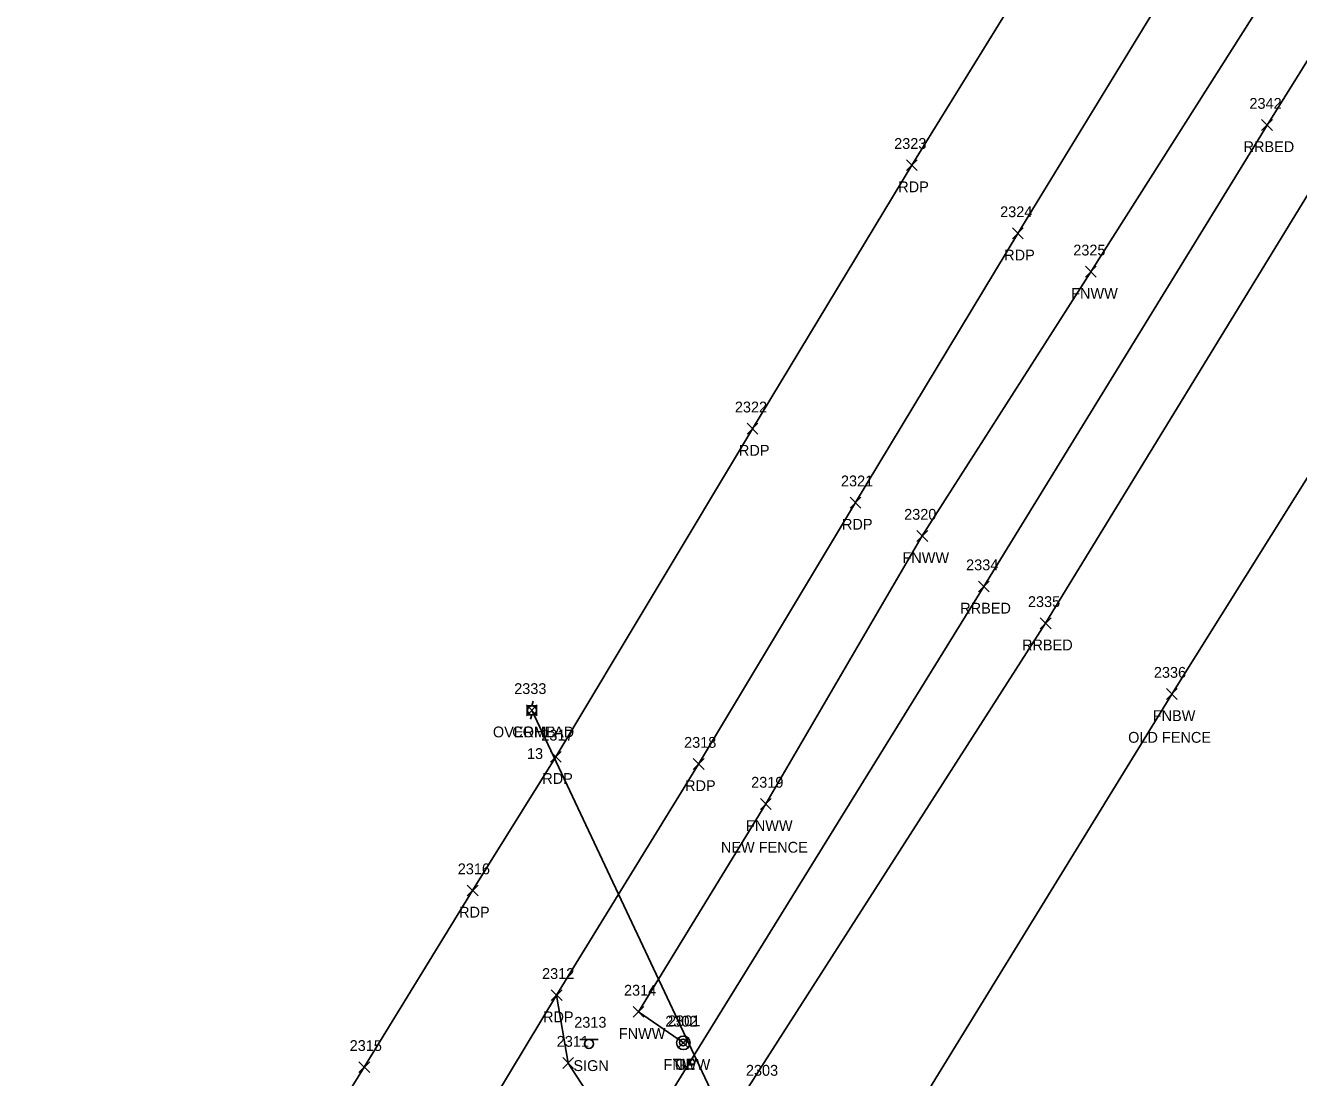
# Model space of a CAD drawing. Extents: x 1508122 to 1515053, y 865012 to 875267.
# Drawn here: x 1513728.5 to 1513963.5, y 873736 to 873930.3 of the extents above; entities that cross this region are included whole.
import ezdxf

# ---------------------------------------------------------------- set-up
doc = ezdxf.new("R2010")
doc.units = 0
for name, color, linetype in [('C_A', 7, 'Continuous'), ('C_I', 7, 'Continuous'), ('CBP', 7, 'Continuous'), ('L_A', 7, 'Continuous'), ('L_C', 7, 'Continuous'), ('L_I', 7, 'Continuous'), ('L_TIC', 7, 'Continuous'), ('LFNC', 7, 'Continuous'), ('P_A', 7, 'Continuous'), ('P_I', 7, 'Continuous'), ('P_TIC', 7, 'Continuous'), ('PET', 7, 'Continuous'), ('R_A', 7, 'Continuous'), ('R_I', 7, 'Continuous'), ('R_TIC', 7, 'Continuous'), ('RGP', 7, 'Continuous'), ('RRB', 7, 'Continuous'), ('S_A', 7, 'Continuous'), ('S_I', 7, 'Continuous'), ('SSGN', 7, 'Continuous'), ('U_A', 7, 'Continuous'), ('U_C', 7, 'Continuous'), ('U_I', 7, 'Continuous'), ('U_TIC', 7, 'Continuous'), ('UP', 7, 'Continuous'), ('UT', 7, 'Continuous')]:
    doc.layers.add(name, color=color, linetype=linetype)

msp = doc.modelspace()

# ---------------------------------------------------------------- linework, layer by layer
at = {"layer": 'CBP'}
for radius in [0.625, 0.0833]:
    msp.add_circle((1513849.87, 873742.45), radius, dxfattribs=at)
at = {"layer": 'L_TIC'}
for points in [[(1513924.17, 873883.81), (1513926.17, 873885.81)], [(1513926.17, 873883.81), (1513924.17, 873885.81)], [(1513893.04, 873835), (1513895.04, 873837)], [(1513895.04, 873835), (1513893.04, 873837)], [(1513939.11, 873805.81), (1513941.11, 873807.81)], [(1513941.11, 873805.81), (1513939.11, 873807.81)], [(1513864.15, 873785.51), (1513866.15, 873787.51)], [(1513866.15, 873785.51), (1513864.15, 873787.51)], [(1513840.67, 873747.1), (1513842.67, 873749.1)], [(1513842.67, 873747.1), (1513840.67, 873749.1)], [(1513848.94, 873741.38), (1513850.94, 873743.38)], [(1513850.94, 873741.38), (1513848.94, 873743.38)]]:
    msp.add_lwpolyline(points, dxfattribs=at)
at = {"layer": 'LFNC'}
for points in [[(1513849.94, 873742.38), (1513841.67, 873748.1), (1513865.15, 873786.51), (1513894.04, 873836), (1513925.17, 873884.81), (1513957.31, 873935.58), (1513979.46, 873971.1), (1514010.28, 874020.55), (1514050.39, 874085.13), (1514079.4, 874132.28), (1514109.16, 874179.83), (1514120.56, 874178.77)], [(1513883.96, 873715.43), (1513940.11, 873806.81), (1513990.41, 873887.15)]]:
    msp.add_lwpolyline(points, dxfattribs=at)
at = {"layer": 'P_TIC'}
for points in [[(1513891.11, 873903.49), (1513893.11, 873905.49)], [(1513893.11, 873903.49), (1513891.11, 873905.49)], [(1513910.67, 873890.89), (1513912.67, 873892.89)], [(1513912.67, 873890.89), (1513910.67, 873892.89)], [(1513861.7, 873854.82), (1513863.7, 873856.82)], [(1513863.7, 873854.82), (1513861.7, 873856.82)], [(1513880.72, 873841.17), (1513882.72, 873843.17)], [(1513882.72, 873841.17), (1513880.72, 873843.17)], [(1513825.41, 873794.21), (1513827.41, 873796.21)], [(1513827.41, 873794.21), (1513825.41, 873796.21)], [(1513851.76, 873792.88), (1513853.76, 873794.88)], [(1513853.76, 873792.88), (1513851.76, 873794.88)], [(1513810.04, 873769.52), (1513812.04, 873771.52)], [(1513812.04, 873769.52), (1513810.04, 873771.52)], [(1513825.54, 873750.18), (1513827.54, 873752.18)], [(1513827.54, 873750.18), (1513825.54, 873752.18)], [(1513825.54, 873750.18), (1513827.54, 873752.18)], [(1513827.54, 873750.18), (1513825.54, 873752.18)], [(1513790.03, 873736.88), (1513792.03, 873738.88)], [(1513792.03, 873736.88), (1513790.03, 873738.88)], [(1513827.68, 873737.66), (1513829.68, 873739.66)], [(1513829.68, 873737.66), (1513827.68, 873739.66)]]:
    msp.add_lwpolyline(points, dxfattribs=at)
at = {"layer": 'PET'}
for points in [[(1513466.17, 873213.07), (1513500.31, 873271.08), (1513533.51, 873325.85), (1513565.92, 873377.51), (1513601.02, 873434.43), (1513630.8, 873481.59), (1513663.12, 873532.69), (1513695.04, 873583.32), (1513791.03, 873737.88), (1513811.04, 873770.52), (1513826.41, 873795.21), (1513862.7, 873855.82), (1513892.11, 873904.49), (1513923.1, 873954.81)], [(1513455.04, 873151.27), (1513485.29, 873202.33), (1513519.6, 873259.87), (1513551.9, 873312.77), (1513584.37, 873365.63), (1513617.09, 873418.81), (1513648.76, 873468.83), (1513681.49, 873520.59), (1513713.49, 873570.94), (1513800.66, 873708.29), (1513826.54, 873751.18), (1513852.76, 873793.88), (1513881.72, 873842.17), (1513911.67, 873891.89), (1513942.82, 873942.89)], [(1513824.54, 873545.65), (1513854.29, 873593.15), (1513872.35, 873622.16), (1513878.19, 873633.02), (1513885.6, 873656.94), (1513886.44, 873668.48), (1513875.83, 873692.09), (1513868.29, 873700.88), (1513850.37, 873716.18), (1513841.18, 873722.67), (1513834.12, 873730.17), (1513828.68, 873738.66), (1513826.54, 873751.18)]]:
    msp.add_lwpolyline(points, dxfattribs=at)
at = {"layer": 'R_TIC'}
for points in [[(1513956.69, 873910.9), (1513958.69, 873912.9)], [(1513958.69, 873910.9), (1513956.69, 873912.9)], [(1513904.39, 873825.67), (1513906.39, 873827.67)], [(1513906.39, 873825.67), (1513904.39, 873827.67)], [(1513915.81, 873818.88), (1513917.81, 873820.88)], [(1513917.81, 873818.88), (1513915.81, 873820.88)]]:
    msp.add_lwpolyline(points, dxfattribs=at)
at = {"layer": 'RGP'}
msp.add_line((1513849.94, 873742.38), (1513849.94, 873742.38), dxfattribs=at)
for radius in [1.25, 0.0833]:
    msp.add_circle((1513849.94, 873742.38), radius, dxfattribs=at)
at = {"layer": 'RRB'}
for points in [[(1513228.31, 872677.99), (1513247.91, 872725.05), (1513270.86, 872775.34), (1513289.12, 872813.81), (1513319.1, 872873.87), (1513347.47, 872925.52), (1513374.77, 872971.44), (1513393.49, 873000.11), (1513437.27, 873071.02), (1513458.13, 873103.89), (1513504.32, 873179.38), (1513525.85, 873213.8), (1513574, 873293.73), (1513619.17, 873366.93), (1513650.95, 873417.63), (1513697.43, 873492.91), (1513723.07, 873532.74), (1513749.97, 873575.84), (1513797.76, 873652.14), (1513828.99, 873702.68), (1513841.18, 873722.67), (1513905.39, 873826.67), (1513957.69, 873911.9), (1513997.47, 873975.73)], [(1513240.34, 872672.59), (1513259.24, 872718.12), (1513282.12, 872769.92), (1513300.61, 872809.77), (1513331.29, 872869.64), (1513358.47, 872918.38), (1513387.89, 872964.97), (1513404.26, 872991.91), (1513448.93, 873064.4), (1513469.17, 873096.67), (1513514.98, 873172.69), (1513538.39, 873208.28), (1513585.22, 873287.66), (1513630.12, 873359.27), (1513661.28, 873410.15), (1513709.31, 873487.04), (1513733.32, 873526.23), (1513760.83, 873569.62), (1513809.55, 873645.89), (1513841.33, 873697.41), (1513850.37, 873716.18), (1513916.81, 873819.88), (1513968.56, 873904.51), (1514007.95, 873968.59)]]:
    msp.add_lwpolyline(points, dxfattribs=at)
at = {"layer": 'SSGN'}
for p, q in [((1513830.85, 873743.03), (1513834.19, 873743.03)), ((1513832.5, 873742.2), (1513832.5, 873742.2))]:
    msp.add_line(p, q, dxfattribs=at)
msp.add_circle((1513832.5, 873742.2), 0.833, dxfattribs=at)
at = {"layer": 'U_TIC'}
for points in [[(1513820.97, 873802.81), (1513822.97, 873804.81)], [(1513822.97, 873802.81), (1513820.97, 873804.81)]]:
    msp.add_lwpolyline(points, dxfattribs=at)
at = {"layer": 'UP'}
for p, q in [((1513821.13, 873802.98), (1513821.13, 873804.64)), ((1513821.13, 873804.64), (1513822.8, 873804.64)), ((1513822.22, 873805.48), (1513821.97, 873804.64)), ((1513822.8, 873804.64), (1513822.8, 873802.98)), ((1513822.8, 873802.98), (1513821.13, 873802.98)), ((1513821.72, 873802.14), (1513821.97, 873802.98)), ((1513821.97, 873803.81), (1513821.97, 873803.81))]:
    msp.add_line(p, q, dxfattribs=at)
msp.add_circle((1513821.97, 873803.81), 0.833, dxfattribs=at)
at = {"layer": 'UT'}
msp.add_lwpolyline([(1513894.86, 873648.9), (1513821.97, 873803.81)], dxfattribs=at)

# ---------------------------------------------------------------- texts
at = {"layer": 'C_A'}
msp.add_text('TIE', height=2, dxfattribs=at).set_placement((1513847.95, 873737.45))
at = {"layer": 'C_I'}
msp.add_text('2301', height=2, dxfattribs=at).set_placement((1513847.1, 873745.45))
at = {"layer": 'L_A'}
for s, p in [('FNWW', (1513921.52, 873879.81)), ('FNWW', (1513890.38, 873831)), ('FNBW', (1513936.58, 873801.81)), ('FNWW', (1513861.49, 873781.51)), ('FNWW', (1513838.02, 873743.1)), ('FNWW', (1513846.28, 873737.38))]:
    msp.add_text(s, height=2, dxfattribs=at).set_placement(p)
at = {"layer": 'L_C'}
for s, p in [('OLD FENCE', (1513932.04, 873797.81)), ('NEW FENCE', (1513856.86, 873777.51))]:
    msp.add_text(s, height=2, dxfattribs=at).set_placement(p)
at = {"layer": 'L_I'}
for s, p in [('2325', (1513921.91, 873887.81)), ('2320', (1513890.69, 873839)), ('2336', (1513936.79, 873809.81)), ('2319', (1513862.45, 873789.51)), ('2314', (1513838.98, 873751.1)), ('2302', (1513846.6, 873745.38))]:
    msp.add_text(s, height=2, dxfattribs=at).set_placement(p)
at = {"layer": 'P_A'}
for p in [(1513889.6, 873899.49), (1513909.16, 873886.89), (1513860.19, 873850.82), (1513879.21, 873837.17), (1513823.89, 873790.21), (1513850.25, 873788.88), (1513808.53, 873765.52), (1513824.03, 873746.18), (1513824.03, 873746.18)]:
    msp.add_text('RDP', height=2, dxfattribs=at).set_placement(p)
at = {"layer": 'P_I'}
for s, p in [('2323', (1513888.85, 873907.49)), ('2324', (1513908.41, 873894.89)), ('2322', (1513859.44, 873858.82)), ('2321', (1513879.03, 873845.17)), ('2317', (1513823.71, 873798.21)), ('2318', (1513850.07, 873796.88)), ('2316', (1513808.29, 873773.52)), ('2312', (1513823.85, 873754.18)), ('2312', (1513823.85, 873754.18)), ('2311', (1513826.56, 873741.66)), ('2315', (1513788.34, 873740.88))]:
    msp.add_text(s, height=2, dxfattribs=at).set_placement(p)
at = {"layer": 'R_A'}
for s, p in [('RRBED', (1513953.34, 873906.9)), ('RRBED', (1513901.04, 873821.67)), ('RRBED', (1513912.45, 873814.88)), ('GP', (1513848.37, 873737.38))]:
    msp.add_text(s, height=2, dxfattribs=at).set_placement(p)
at = {"layer": 'R_I'}
for s, p in [('2342', (1513954.43, 873914.9)), ('2334', (1513902.13, 873829.67)), ('2335', (1513913.55, 873822.88)), ('2302', (1513846.6, 873745.38)), ('2303', (1513861.48, 873736.31))]:
    msp.add_text(s, height=2, dxfattribs=at).set_placement(p)
at = {"layer": 'S_A'}
msp.add_text('SIGN', height=2, dxfattribs=at).set_placement((1513829.64, 873737.18))
at = {"layer": 'S_I'}
msp.add_text('2313', height=2, dxfattribs=at).set_placement((1513829.79, 873745.18))
at = {"layer": 'U_A'}
for s, p in [('OVERHEAD', (1513814.78, 873798.81)), ('COMB', (1513818.35, 873798.81))]:
    msp.add_text(s, height=2, dxfattribs=at).set_placement(p)
at = {"layer": 'U_C'}
msp.add_text('13', height=2, dxfattribs=at).set_placement((1513821.07, 873794.81))
at = {"layer": 'U_I'}
msp.add_text('2333', height=2, dxfattribs=at).set_placement((1513818.71, 873806.81))
msp.add_text('2333', height=2, dxfattribs=at).set_placement((1513818.71, 873806.81))

doc.saveas('drawing.dxf')
